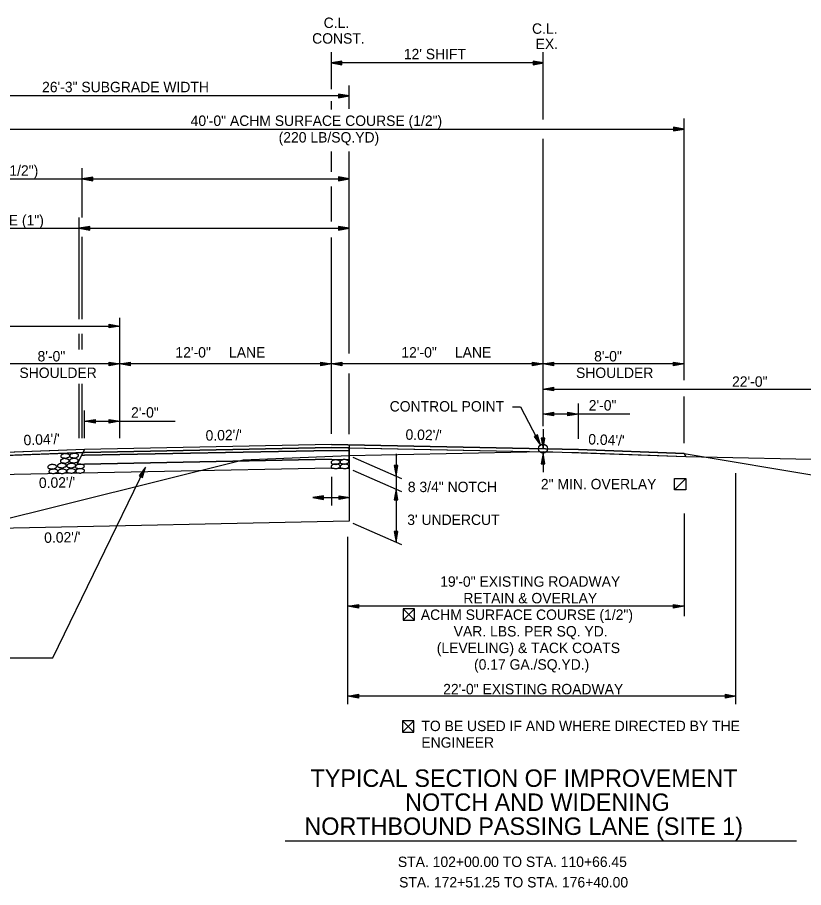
# Model space of a CAD drawing. Extents: x 1398565 to 1398920, y 1968324 to 1968581.
# Drawn here: x 1398623.06 to 1398667.63, y 1968531.8 to 1968581.13 of the extents above; entities that cross this region are included whole.
import ezdxf

# ---------------------------------------------------------------- set-up
doc = ezdxf.new("R2010")
doc.units = 0
for name, color, linetype in [('1', 7, 'Continuous'), ('10', 7, 'Continuous'), ('19', 7, 'Continuous'), ('42', 7, 'Continuous'), ('7', 7, 'Continuous'), ('Level 1', 7, 'Continuous'), ('Level 9', 7, 'Continuous')]:
    doc.layers.add(name, color=color, linetype=linetype)

# ---------------------------------------------------------------- blocks, each defined once
blk = doc.blocks.new('ROCKS')
at = {"layer": '1'}
blk.add_spline([(0.013, 0.06), (0.053, 0.053), (0.107, 0.033), (0.133, 0.013), (0.133, -0.007), (0.12, -0.033), (0.107, -0.04), (0.073, -0.053), (0.033, -0.067), (0.013, -0.067), (-0.02, -0.06), (-0.06, -0.053), (-0.087, -0.047), (-0.113, -0.02), (-0.113, -0.007), (-0.107, 0.02), (-0.087, 0.033), (-0.067, 0.047), (-0.033, 0.053), (-0.02, 0.06), (0.013, 0.06)], degree=3, dxfattribs=at)

msp = doc.modelspace()

# ---------------------------------------------------------------- linework, layer by layer
at = {"layer": '10'}
for p, q in [((1398644.93, 1968547.604), (1398645.571, 1968546.963)), ((1398645.571, 1968547.604), (1398644.93, 1968546.963)), ((1398645.311, 1968546.963), (1398645.322, 1968546.963)), ((1398644.887, 1968541.249), (1398645.528, 1968540.608)), ((1398645.528, 1968541.249), (1398644.887, 1968540.608)), ((1398645.269, 1968540.608), (1398645.28, 1968540.608))]:
    msp.add_line(p, q, dxfattribs=at)
for points in [[(1398660.311, 1968555), (1398660.952, 1968555), (1398660.952, 1968554.359), (1398660.311, 1968554.359)], [(1398660.311, 1968555), (1398660.952, 1968555), (1398660.311, 1968554.359)]]:
    msp.add_lwpolyline(points, close=True, dxfattribs=at)
for points in [[(1398645.322, 1968546.963), (1398645.571, 1968546.963), (1398645.571, 1968547.604), (1398644.93, 1968547.604), (1398644.93, 1968546.963), (1398645.311, 1968546.963)], [(1398645.28, 1968540.608), (1398645.528, 1968540.608), (1398645.528, 1968541.249), (1398644.887, 1968541.249), (1398644.887, 1968540.608), (1398645.269, 1968540.608)]]:
    msp.add_lwpolyline(points, dxfattribs=at)
at = {"layer": '19'}
for p, q in [((1398641.459, 1968578.656), (1398640.859, 1968578.551)), ((1398652.859, 1968578.551), (1398640.859, 1968578.551)), ((1398640.859, 1968578.551), (1398641.459, 1968578.446)), ((1398641.459, 1968578.601), (1398641.019, 1968578.566)), ((1398641.019, 1968578.536), (1398641.459, 1968578.496)), ((1398641.459, 1968578.446), (1398641.459, 1968578.656)), ((1398652.289, 1968578.656), (1398652.289, 1968578.446)), ((1398652.889, 1968578.551), (1398652.289, 1968578.656)), ((1398652.729, 1968578.566), (1398652.289, 1968578.601)), ((1398652.289, 1968578.446), (1398652.889, 1968578.551)), ((1398652.289, 1968578.496), (1398652.729, 1968578.536)), ((1398641.859, 1968575.947), (1398641.859, 1968577.276)), ((1398641.859, 1968576.676), (1398615.574, 1968576.676)), ((1398641.259, 1968576.781), (1398641.259, 1968576.571)), ((1398641.859, 1968576.676), (1398641.259, 1968576.781)), ((1398641.699, 1968576.691), (1398641.259, 1968576.726)), ((1398641.259, 1968576.571), (1398641.859, 1968576.676)), ((1398641.259, 1968576.621), (1398641.699, 1968576.661)), ((1398660.859, 1968560.562), (1398660.859, 1968575.401)), ((1398660.259, 1968574.906), (1398660.259, 1968574.696)), ((1398660.859, 1968574.801), (1398660.259, 1968574.906)), ((1398660.699, 1968574.816), (1398660.259, 1968574.851)), ((1398620.859, 1968574.801), (1398660.859, 1968574.801)), ((1398660.259, 1968574.696), (1398660.859, 1968574.801)), ((1398660.259, 1968574.746), (1398660.699, 1968574.786)), ((1398641.859, 1968562.088), (1398641.859, 1968573.53)), ((1398626.732, 1968569.781), (1398626.732, 1968572.579)), ((1398607.966, 1968571.979), (1398641.859, 1968571.979)), ((1398627.332, 1968572.083), (1398626.732, 1968571.979)), ((1398626.732, 1968571.979), (1398627.332, 1968571.873)), ((1398627.332, 1968572.028), (1398626.892, 1968571.994)), ((1398626.892, 1968571.964), (1398627.332, 1968571.923)), ((1398627.332, 1968571.873), (1398627.332, 1968572.083)), ((1398641.259, 1968572.084), (1398641.259, 1968571.874)), ((1398641.859, 1968571.979), (1398641.259, 1968572.084)), ((1398641.699, 1968571.994), (1398641.259, 1968572.029)), ((1398641.259, 1968571.874), (1398641.859, 1968571.979)), ((1398641.259, 1968571.924), (1398641.699, 1968571.964)), ((1398626.562, 1968564.026), (1398626.562, 1968569.781)), ((1398609.436, 1968569.181), (1398641.859, 1968569.181)), ((1398627.162, 1968569.286), (1398626.562, 1968569.181)), ((1398626.562, 1968569.181), (1398627.162, 1968569.076)), ((1398627.162, 1968569.231), (1398626.722, 1968569.196)), ((1398626.722, 1968569.166), (1398627.162, 1968569.126)), ((1398627.162, 1968569.076), (1398627.162, 1968569.286)), ((1398641.259, 1968569.286), (1398641.259, 1968569.076)), ((1398641.859, 1968569.181), (1398641.259, 1968569.286)), ((1398641.699, 1968569.196), (1398641.259, 1968569.231)), ((1398641.259, 1968569.076), (1398641.859, 1968569.181)), ((1398641.259, 1968569.126), (1398641.699, 1968569.166)), ((1398626.732, 1968564.026), (1398626.732, 1968568.694)), ((1398628.859, 1968557.282), (1398628.859, 1968564.104)), ((1398604.859, 1968563.63), (1398628.859, 1968563.63)), ((1398628.259, 1968563.525), (1398628.259, 1968563.735)), ((1398628.259, 1968563.735), (1398628.859, 1968563.63)), ((1398628.259, 1968563.68), (1398628.699, 1968563.645)), ((1398628.859, 1968563.63), (1398628.259, 1968563.525)), ((1398628.699, 1968563.615), (1398628.259, 1968563.575)), ((1398626.562, 1968562.311), (1398626.562, 1968563.195)), ((1398626.732, 1968562.311), (1398626.732, 1968563.195)), ((1398628.259, 1968561.38), (1398628.259, 1968561.59)), ((1398628.259, 1968561.59), (1398628.859, 1968561.485)), ((1398628.259, 1968561.535), (1398628.699, 1968561.5)), ((1398628.859, 1968561.485), (1398629.459, 1968561.59)), ((1398629.019, 1968561.5), (1398629.459, 1968561.535)), ((1398629.459, 1968561.59), (1398629.459, 1968561.38)), ((1398640.259, 1968561.38), (1398640.259, 1968561.59)), ((1398640.259, 1968561.59), (1398640.859, 1968561.485)), ((1398640.259, 1968561.535), (1398640.699, 1968561.5)), ((1398640.859, 1968561.485), (1398641.459, 1968561.59)), ((1398641.019, 1968561.5), (1398641.459, 1968561.535)), ((1398641.459, 1968561.59), (1398641.459, 1968561.38)), ((1398652.259, 1968561.38), (1398652.259, 1968561.59)), ((1398652.259, 1968561.59), (1398652.859, 1968561.485)), ((1398652.259, 1968561.535), (1398652.699, 1968561.5)), ((1398652.859, 1968561.485), (1398653.459, 1968561.59)), ((1398653.019, 1968561.5), (1398653.459, 1968561.535)), ((1398653.459, 1968561.59), (1398653.459, 1968561.38)), ((1398660.259, 1968561.38), (1398660.259, 1968561.59)), ((1398660.259, 1968561.59), (1398660.859, 1968561.485)), ((1398660.259, 1968561.535), (1398660.699, 1968561.5)), ((1398640.859, 1968561.485), (1398615.574, 1968561.485)), ((1398628.859, 1968561.485), (1398628.259, 1968561.38)), ((1398628.699, 1968561.47), (1398628.259, 1968561.43)), ((1398629.459, 1968561.38), (1398628.859, 1968561.485)), ((1398629.459, 1968561.43), (1398629.019, 1968561.47)), ((1398640.859, 1968561.485), (1398640.259, 1968561.38)), ((1398640.699, 1968561.47), (1398640.259, 1968561.43)), ((1398660.859, 1968561.485), (1398640.859, 1968561.485)), ((1398641.459, 1968561.38), (1398640.859, 1968561.485)), ((1398641.459, 1968561.43), (1398641.019, 1968561.47)), ((1398652.859, 1968561.485), (1398652.259, 1968561.38)), ((1398652.699, 1968561.47), (1398652.259, 1968561.43)), ((1398653.459, 1968561.38), (1398652.859, 1968561.485)), ((1398653.459, 1968561.43), (1398653.019, 1968561.47)), ((1398660.859, 1968561.485), (1398660.259, 1968561.38)), ((1398660.699, 1968561.47), (1398660.259, 1968561.43)), ((1398641.859, 1968557.502), (1398641.859, 1968560.953)), ((1398626.562, 1968557.282), (1398626.562, 1968560.366)), ((1398626.732, 1968557.282), (1398626.732, 1968560.366)), ((1398652.859, 1968560.064), (1398653.459, 1968560.169)), ((1398652.859, 1968560.064), (1398674.859, 1968560.064)), ((1398653.459, 1968559.959), (1398652.859, 1968560.064)), ((1398653.019, 1968560.079), (1398653.459, 1968560.114)), ((1398653.459, 1968560.009), (1398653.019, 1968560.049)), ((1398653.459, 1968560.169), (1398653.459, 1968559.959)), ((1398660.859, 1968557.002), (1398660.859, 1968559.645)), ((1398654.859, 1968557.242), (1398654.859, 1968559.243)), ((1398626.859, 1968557.282), (1398626.859, 1968558.839)), ((1398652.859, 1968558.643), (1398653.459, 1968558.748)), ((1398657.785, 1968558.643), (1398652.859, 1968558.643)), ((1398653.459, 1968558.538), (1398652.859, 1968558.643)), ((1398653.019, 1968558.658), (1398653.459, 1968558.693)), ((1398653.459, 1968558.588), (1398653.019, 1968558.628)), ((1398653.459, 1968558.748), (1398653.459, 1968558.538)), ((1398654.259, 1968558.538), (1398654.259, 1968558.748)), ((1398654.259, 1968558.748), (1398654.859, 1968558.643)), ((1398654.259, 1968558.693), (1398654.699, 1968558.658)), ((1398654.859, 1968558.643), (1398654.259, 1968558.538)), ((1398654.699, 1968558.628), (1398654.259, 1968558.588)), ((1398626.859, 1968558.239), (1398627.459, 1968558.345)), ((1398626.859, 1968558.239), (1398632.006, 1968558.239)), ((1398627.459, 1968558.135), (1398626.859, 1968558.239)), ((1398627.019, 1968558.254), (1398627.459, 1968558.29)), ((1398627.459, 1968558.185), (1398627.019, 1968558.224)), ((1398627.459, 1968558.345), (1398627.459, 1968558.135)), ((1398628.259, 1968558.134), (1398628.259, 1968558.344)), ((1398628.259, 1968558.344), (1398628.859, 1968558.239)), ((1398628.259, 1968558.289), (1398628.699, 1968558.254)), ((1398628.859, 1968558.239), (1398628.259, 1968558.134)), ((1398628.699, 1968558.224), (1398628.259, 1968558.184)), ((1398652.859, 1968557.79), (1398652.859, 1968556.682)), ((1398652.536, 1968557.467), (1398652.35, 1968557.373)), ((1398652.35, 1968557.373), (1398652.714, 1968556.885)), ((1398652.392, 1968557.39), (1398652.628, 1968557.022)), ((1398652.651, 1968557.031), (1398652.49, 1968557.439)), ((1398652.714, 1968556.885), (1398652.536, 1968557.467)), ((1398652.964, 1968557.282), (1398652.754, 1968557.282)), ((1398652.754, 1968557.282), (1398652.859, 1968556.682)), ((1398652.809, 1968557.282), (1398652.844, 1968556.842)), ((1398652.859, 1968556.682), (1398652.964, 1968557.282)), ((1398652.874, 1968556.842), (1398652.914, 1968557.282)), ((1398626.859, 1968556.642), (1398620.859, 1968556.402)), ((1398626.859, 1968556.642), (1398626.774, 1968556.472)), ((1398640.859, 1968556.922), (1398626.859, 1968556.642)), ((1398640.859, 1968556.755), (1398626.859, 1968556.475)), ((1398640.859, 1968556.588), (1398626.859, 1968556.308)), ((1398640.859, 1968556.588), (1398626.859, 1968556.308)), ((1398640.859, 1968556.922), (1398654.859, 1968556.642)), ((1398640.859, 1968556.755), (1398641.859, 1968556.735)), ((1398640.859, 1968556.588), (1398641.859, 1968556.568)), ((1398641.859, 1968556.568), (1398640.859, 1968556.588)), ((1398641.859, 1968556.902), (1398641.859, 1968555.276)), ((1398641.859, 1968556.735), (1398654.859, 1968556.475)), ((1398654.859, 1968556.642), (1398660.859, 1968556.402)), ((1398626.859, 1968556.475), (1398620.774, 1968556.232)), ((1398626.689, 1968556.302), (1398626.434, 1968555.791)), ((1398626.774, 1968556.472), (1398626.689, 1968556.302)), ((1398626.859, 1968556.308), (1398626.689, 1968556.302)), ((1398641.859, 1968556.068), (1398641.859, 1968556.568)), ((1398642.084, 1968556.196), (1398644.827, 1968554.986)), ((1398644.525, 1968556.398), (1398644.525, 1968555.123)), ((1398652.859, 1968556.432), (1398652.754, 1968555.832)), ((1398652.844, 1968556.272), (1398652.809, 1968555.832)), ((1398652.964, 1968555.832), (1398652.859, 1968556.432)), ((1398652.859, 1968556.432), (1398652.859, 1968555.349)), ((1398652.914, 1968555.832), (1398652.874, 1968556.272)), ((1398654.859, 1968556.475), (1398660.944, 1968556.232)), ((1398660.859, 1968556.402), (1398674.859, 1968554.068)), ((1398660.859, 1968556.402), (1398660.944, 1968556.232)), ((1398625.067, 1968544.829), (1398630.328, 1968555.636)), ((1398626.859, 1968555.808), (1398626.434, 1968555.791)), ((1398640.859, 1968556.088), (1398626.859, 1968555.808)), ((1398630.328, 1968555.636), (1398629.964, 1968555.147)), ((1398630.151, 1968555.055), (1398630.328, 1968555.636)), ((1398640.859, 1968556.088), (1398641.859, 1968556.068)), ((1398640.859, 1968556.088), (1398641.859, 1968556.068)), ((1398641.859, 1968556.068), (1398641.859, 1968556.068)), ((1398644.63, 1968555.723), (1398644.42, 1968555.723)), ((1398644.42, 1968555.723), (1398644.525, 1968555.123)), ((1398644.475, 1968555.723), (1398644.51, 1968555.283)), ((1398644.525, 1968555.123), (1398644.63, 1968555.723)), ((1398644.54, 1968555.283), (1398644.58, 1968555.723)), ((1398652.754, 1968555.832), (1398652.964, 1968555.832)), ((1398640.859, 1968555.586), (1398615.574, 1968555.08)), ((1398629.964, 1968555.147), (1398630.151, 1968555.055)), ((1398630.245, 1968555.5), (1398630.013, 1968555.126)), ((1398630.107, 1968555.078), (1398630.27, 1968555.487)), ((1398640.859, 1968555.586), (1398641.859, 1968555.566)), ((1398641.859, 1968555.276), (1398641.859, 1968552.566)), ((1398642.084, 1968555.467), (1398644.827, 1968554.257)), ((1398644.525, 1968555.123), (1398644.525, 1968551.39)), ((1398663.796, 1968542.194), (1398663.796, 1968555.304)), ((1398644.525, 1968554.39), (1398644.42, 1968553.79)), ((1398644.51, 1968554.23), (1398644.475, 1968553.79)), ((1398644.63, 1968553.79), (1398644.525, 1968554.39)), ((1398644.58, 1968553.79), (1398644.54, 1968554.23)), ((1398644.42, 1968553.79), (1398644.63, 1968553.79)), ((1398660.859, 1968553.017), (1398660.859, 1968547.195)), ((1398641.859, 1968552.566), (1398603.022, 1968551.789)), ((1398642.084, 1968552.467), (1398644.827, 1968551.257)), ((1398641.796, 1968542.194), (1398641.796, 1968551.695)), ((1398644.63, 1968551.99), (1398644.42, 1968551.99)), ((1398644.42, 1968551.99), (1398644.525, 1968551.39)), ((1398644.475, 1968551.99), (1398644.51, 1968551.55)), ((1398644.525, 1968551.39), (1398644.63, 1968551.99)), ((1398644.54, 1968551.55), (1398644.58, 1968551.99)), ((1398641.796, 1968547.751), (1398642.396, 1968547.856)), ((1398642.396, 1968547.646), (1398641.796, 1968547.751)), ((1398660.859, 1968547.751), (1398641.796, 1968547.751)), ((1398641.956, 1968547.766), (1398642.396, 1968547.801)), ((1398642.396, 1968547.696), (1398641.956, 1968547.736)), ((1398642.396, 1968547.856), (1398642.396, 1968547.646)), ((1398660.259, 1968547.646), (1398660.259, 1968547.856)), ((1398660.259, 1968547.856), (1398660.859, 1968547.751)), ((1398660.259, 1968547.801), (1398660.699, 1968547.766)), ((1398660.859, 1968547.751), (1398660.259, 1968547.646)), ((1398660.699, 1968547.736), (1398660.259, 1968547.696)), ((1398621.539, 1968544.829), (1398625.067, 1968544.829)), ((1398641.796, 1968542.656), (1398642.396, 1968542.761)), ((1398663.796, 1968542.656), (1398641.796, 1968542.656)), ((1398642.396, 1968542.551), (1398641.796, 1968542.656)), ((1398641.956, 1968542.671), (1398642.396, 1968542.706)), ((1398642.396, 1968542.601), (1398641.956, 1968542.641)), ((1398642.396, 1968542.761), (1398642.396, 1968542.551)), ((1398663.196, 1968542.551), (1398663.196, 1968542.761)), ((1398663.196, 1968542.761), (1398663.796, 1968542.656)), ((1398663.196, 1968542.706), (1398663.636, 1968542.671)), ((1398663.796, 1968542.656), (1398663.196, 1968542.551)), ((1398663.636, 1968542.641), (1398663.196, 1968542.601)), ((1398638.24, 1968534.455), (1398667.22, 1968534.455))]:
    msp.add_line(p, q, dxfattribs=at)
for points in [[(1398651.134, 1968559.062), (1398651.58, 1968559.062), (1398652.714, 1968556.885)], [(1398626.859, 1968556.308), (1398626.689, 1968556.302), (1398626.434, 1968555.791)], [(1398626.434, 1968555.791), (1398626.859, 1968555.808), (1398640.859, 1968556.088)]]:
    msp.add_lwpolyline(points, dxfattribs=at)
for points in [[(1398620.777, 1968556.237), (1398626.859, 1968556.475), (1398640.859, 1968556.755), (1398654.859, 1968556.475), (1398660.944, 1968556.232), (1398660.859, 1968556.402), (1398654.859, 1968556.642), (1398640.859, 1968556.922), (1398626.859, 1968556.642), (1398620.859, 1968556.402)], [(1398626.774, 1968556.472), (1398626.689, 1968556.302), (1398626.859, 1968556.308), (1398640.859, 1968556.588), (1398641.859, 1968556.568), (1398641.859, 1968556.735), (1398640.859, 1968556.755), (1398626.859, 1968556.475)]]:
    msp.add_lwpolyline(points, close=True, dxfattribs=at)
at = {"layer": '42'}
for p, q in [((1398640.859, 1968555.088), (1398640.859, 1968553.456)), ((1398640.412, 1968554.013), (1398639.812, 1968553.908)), ((1398639.812, 1968553.908), (1398640.412, 1968553.803)), ((1398639.812, 1968553.908), (1398641.907, 1968553.908)), ((1398640.412, 1968553.958), (1398639.972, 1968553.923)), ((1398639.972, 1968553.893), (1398640.412, 1968553.853)), ((1398640.412, 1968553.803), (1398640.412, 1968554.013)), ((1398641.307, 1968553.803), (1398641.307, 1968554.013)), ((1398641.307, 1968554.013), (1398641.907, 1968553.908)), ((1398641.307, 1968553.958), (1398641.747, 1968553.923)), ((1398641.907, 1968553.908), (1398641.307, 1968553.803)), ((1398641.747, 1968553.893), (1398641.307, 1968553.853))]:
    msp.add_line(p, q, dxfattribs=at)
for points in [[(1398564.837, 1968549.946), (1398611.333, 1968549.946), (1398635.859, 1968556.055), (1398641.859, 1968556.295)], [(1398641.859, 1968556.295), (1398652.859, 1968556.515)], [(1398652.859, 1968556.515), (1398660.944, 1968556.232), (1398669.859, 1968556.055), (1398678.715, 1968553.595), (1398683.795, 1968554.136), (1398700.612, 1968554.047)]]:
    msp.add_lwpolyline(points, dxfattribs=at)
at = {"layer": '7'}
for p, q in [((1398640.859, 1968577.056), (1398640.859, 1968579.151)), ((1398652.859, 1968575.352), (1398652.859, 1968579.151)), ((1398640.859, 1968575.907), (1398640.859, 1968576.382)), ((1398652.859, 1968557.958), (1398652.859, 1968574.243)), ((1398640.859, 1968572.381), (1398640.859, 1968573.53)), ((1398640.859, 1968569.568), (1398640.859, 1968571.549)), ((1398640.859, 1968557.522), (1398640.859, 1968568.656))]:
    msp.add_line(p, q, dxfattribs=at)
at = {"layer": 'Level 9'}
msp.add_circle((1398652.859, 1968556.682), 0.25, dxfattribs=at)

# ---------------------------------------------------------------- block references
at = {"layer": 'Level 1', "xscale": 2.011654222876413, "yscale": 2.011654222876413, "rotation": 1.8263814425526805}
for p in [(1398625.728, 1968555.999), (1398625.755, 1968556.278), (1398626.24, 1968556.011), (1398626.253, 1968556.293), (1398625.017, 1968555.664), (1398625.56, 1968555.734), (1398626.093, 1968555.729), (1398626.584, 1968555.685), (1398641.08, 1968555.93), (1398641.08, 1968555.688), (1398641.578, 1968555.945), (1398641.584, 1968555.688), (1398625.076, 1968555.408), (1398625.581, 1968555.408), (1398626.086, 1968555.429), (1398626.59, 1968555.428)]:
    msp.add_blockref('ROCKS', p, dxfattribs=at)

# ---------------------------------------------------------------- texts
at = {"layer": '10'}
for s, height, p in [('8\'-0" ', 0.59, (1398624.201, 1968561.63)), ('12\'-0" ', 0.59, (1398632.017, 1968561.849)), ('LANE', 0.59, (1398635.055, 1968561.849)), ('12\'-0" ', 0.59, (1398644.826, 1968561.849)), ('LANE', 0.59, (1398647.864, 1968561.849)), ('8\'-0" ', 0.59, (1398655.755, 1968561.63)), ('SHOULDER', 0.59, (1398623.174, 1968560.69)), ('SHOULDER', 0.59, (1398654.728, 1968560.69)), ('22\'-0"', 0.59, (1398663.573, 1968560.193)), ('CONTROL POINT', 0.59001, (1398644.164, 1968558.79)), ('2\'-0"', 0.59, (1398655.448, 1968558.847)), ('2\'-0"', 0.59, (1398629.502, 1968558.443)), ('8 3/4" NOTCH', 0.59001, (1398645.193, 1968554.222)), ('2" MIN. OVERLAY', 0.59001, (1398652.735, 1968554.381)), ("3' UNDERCUT", 0.59001, (1398645.16, 1968552.36)), ('19\'-0" EXISTING ROADWAY', 0.59001, (1398647.026, 1968548.858)), ('RETAIN & OVERLAY', 0.59001, (1398648.341, 1968547.918)), ('ACHM SURFACE COURSE (1/2")', 0.59001, (1398645.93, 1968546.978)), ('VAR. LBS. PER SQ. YD.', 0.59001, (1398647.793, 1968546.038)), ('(LEVELING) & TACK COATS', 0.59001, (1398646.831, 1968545.098)), ('(0.17 GA./SQ.YD.)', 0.59001, (1398648.945, 1968544.158)), ('22\'-0" EXISTING ROADWAY', 0.59001, (1398647.196, 1968542.761)), ('TO BE USED IF AND WHERE DIRECTED BY THE ', 0.59001, (1398645.96, 1968540.675)), ('ENGINEER', 0.59, (1398645.96, 1968539.735)), ('STA. 102+00.00 TO STA. 110+66.45', 0.59001, (1398644.63, 1968532.971)), ('STA. 172+51.25 TO STA. 176+40.00', 0.59001, (1398644.698, 1968531.813))]:
    msp.add_text(s, height=height, rotation=360, dxfattribs=at).set_placement(p)
at = {"layer": '19'}
for p in [(1398640.422, 1968580.531), (1398652.233, 1968580.201)]:
    msp.add_text('C.L.', height=0.59, dxfattribs=at).set_placement(p)
for s, height, rotation, p in [('CONST.', 0.59, 360, (1398639.768, 1968579.643)), ('EX.', 0.59, 360, (1398652.438, 1968579.333)), ("12' SHIFT", 0.59, 360, (1398644.964, 1968578.757)), ("0.04'/'", 0.59, 2.2906, (1398623.42, 1968556.873)), ("0.02'/'", 0.59, 1.1458, (1398633.734, 1968557.136)), ("0.02'/'", 0.59, 358.8542, (1398645.058, 1968557.194)), ("0.04'/'", 0.59, 357.7094, (1398655.412, 1968556.931)), ("0.02'/'", 0.59, 1.1458, (1398624.284, 1968554.451)), ("0.02'/'", 0.59, 1.1458, (1398624.582, 1968551.343)), ('TYPICAL SECTION OF IMPROVEMENT', 0.98999, 360, (1398639.677, 1968537.513)), ('NOTCH AND WIDENING', 0.98999, 360, (1398645.04, 1968536.151)), ('NORTHBOUND PASSING LANE (SITE 1)', 0.98999, 360, (1398639.33, 1968534.79))]:
    msp.add_text(s, height=height, rotation=rotation, dxfattribs=at).set_placement(p)
at = {"layer": '42'}
for s, p in [('26\'-3" SUBGRADE WIDTH', (1398624.457, 1968576.889)), ('40\'-0" ACHM SURFACE COURSE (1/2")', (1398632.88, 1968574.978)), ('(220 LB/SQ.YD)', (1398637.869, 1968574.038)), ('15\'-1 1/2" ACHM SURFACE COURSE (1/2")', (1398608.67, 1968572.157)), ('15\'-3 1/2" ACHM BINDER COURSE (1")', (1398610.432, 1968569.339))]:
    msp.add_text(s, height=0.59001, rotation=360, dxfattribs=at).set_placement(p)

doc.saveas('drawing.dxf')
